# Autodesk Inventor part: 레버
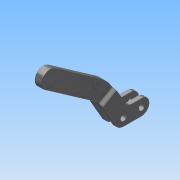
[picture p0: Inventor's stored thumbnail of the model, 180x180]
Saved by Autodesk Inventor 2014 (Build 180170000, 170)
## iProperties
Created: 2017-10
Part Number: 레버
Material: 스테인리스강
Document SubType Name: Modeling
Designer: mduedu
Density: 8.08 g/cm^3
Mass: 86.0413 g
Surface Area: 61.4285 cm^2
Volume: 10.6487 cm^3
Appearance: 반광택
Author: mduedu
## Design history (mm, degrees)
sketch "스케치1" dims "d0" = 14
  geometry: L1 (7, 0)-(-7, 0); L2 (-7, 0)-(-7, 16); L3 (-7, 16)-(7, 16); L4 (7, 16)-(7, 0); L5 (26.017, 22.938)-(19.017, 35.062); L6 (19.017, 35.062)-(-3.5, 22.062); L7 (-3.5, 22.062)-(3.5, 9.938); L8 (3.5, 9.938)-(26.017, 22.938); L9 (0, 16)-(22.517, 29); L10 (0, 16)-(0, 0); C1 r 7 at (0, 16); 1 further point
  constraints: 20 end point, 5 parallel, 4 midpoint, 2 perpendicular, 2 tangent, 1 centre point, 1 coincident, 1 horizontal, 1 horizontal alignment, 2 other
  dimensions: "d2" = 16 distance of L9.start point (0, 0); "d3" = 120 deg angle of L9 L10; "d4" = 26 distance of L9.start L9.end
extrude "돌출1" new body sketch "스케치1" stored distance "d5" = 13; taper "d6" = 0 deg
sketch "스케치2"
  geometry: L1 (3.5, 15.959)-(9.5, 15.959); L2 (9.5, 15.959)-(9.5, -44.041); L3 (9.5, -44.041)-(3.5, -44.041); L4 (3.5, -44.041)-(3.5, 15.959); L5 (13, 21.959)-(0, 21.959) reference; 2 further points
  constraints: 8 end point, 2 parallel, 1 horizontal, 1 midpoint, 1 perpendicular, 1 vertical alignment
  dimensions: "d7" = 6 distance between parallel lines of L1 L5; "d8" = 60 distance of L1.end L2.end; "d9" = 6 distance of L2.end L3.end
extrude "돌출2" cut sketch "스케치2" stored distance "d10" = 13; taper "d11" = 0 deg
fillet "모깎기1"
sketch "스케치3"
  geometry: L1 (35.591, 31.711)-(68.712, 79.013); L2 (68.712, 79.013)-(56.425, 87.617); L3 (56.425, 87.617)-(20.717, 36.62); L4 (7, 11.959)-(7, 0) reference; L5 (19.017, 35.062)-(26.017, 22.938) reference; L6 (26.017, 22.938)-(7, 11.959) reference; L7 (-3.5, 22.062)-(19.017, 35.062) reference; L8 (35.591, 31.711)-(20.717, 36.62); L9 (28.154, 34.166)-(62.569, 83.315); A1 r 30 centre (11.017, 48.919) between (26.017, 22.938) and (35.591, 31.711); A2 r 5.327 centre (16.353, 39.675) between (19.017, 35.062) and (20.717, 36.62); 1 further point
  constraints: 10 end point, 4 point on circle, 4 tangent, 2 centre point, 2 midpoint, 1 parallel, 1 perpendicular
  dimensions: "d18" = 60 distance of L9.start L9.end; "d22" = 145 deg angle of L9 L4; "d24" = 30 radius of A1; "d39" = 15 distance of L1.end L2.end
extrude "돌출3" join sketch "스케치3" stored distance "d16" = 6; taper "d17" = 0 deg
fillet "모깎기2"
chamfer "모따기1" distance "d26" = 3.5; stored, may be unused: second distance "d27" = 2, angle "d28" = 45 deg
fillet "모깎기3" dims "d29" = 5
fillet "모깎기4" dims "d30" = 5
sketch "스케치4"
  geometry: C1 r 2.5 at (0, 0); C2 r 2.5 at (-16, 0); A1 r 7 centre (-16, 0) between (-22.062, -3.5) and (-16, -7) reference; 1 further point
  constraints: 2 centre point, 2 coincident
  dimensions: "d31" = 5 diameter of C1; "d32" = 5 diameter of C2 (= d31)
extrude "돌출4" cut sketch "스케치4" stored distance "d33" = 6; taper "d34" = 0 deg
fillet "모깎기5" dims "d38" = 0.5
node "작업 평면1"
node "솔리드1"
